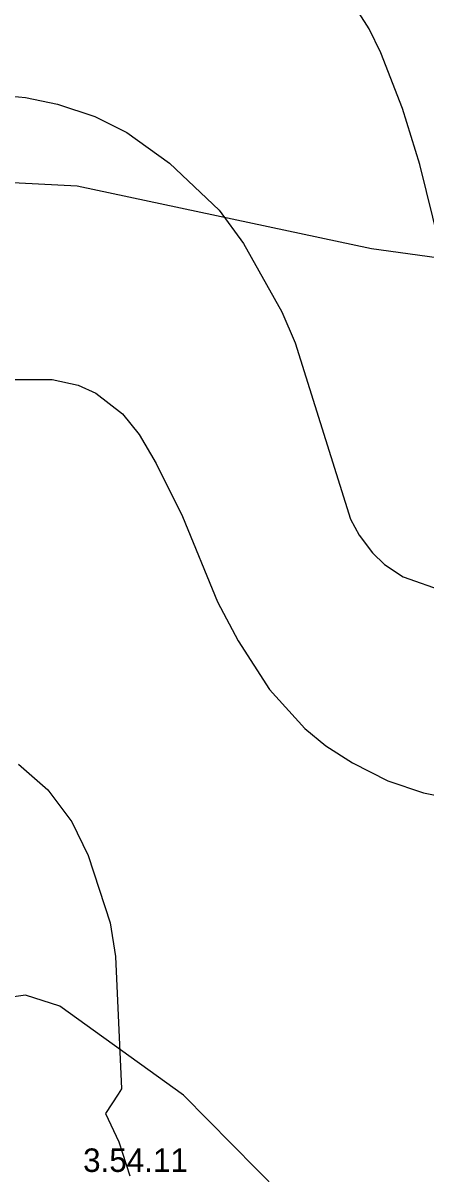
# Model space of a CAD drawing. Extents: x -662500 to -655523, y -1056000 to -1049993.
# Drawn here: x -659925.2 to -659796.6, y -1053965.2 to -1053597.4 of the extents above; entities that cross this region are included whole.
import ezdxf

# ---------------------------------------------------------------- set-up
doc = ezdxf.new("R2010")
doc.units = 0
doc.layers.add('Vrstva 24', color=7, linetype='Continuous')
doc.layers.add('Vrstva 7', color=7, linetype='Continuous')

msp = doc.modelspace()

# ---------------------------------------------------------------- linework, layer by layer
at = {"layer": 'Vrstva 24'}
for points in [[(-659687, -1053701.5), (-659711, -1053686.5), (-659734.5, -1053680.5), (-659814, -1053669.5), (-659908, -1053649.5), (-659980.14, -1053645.8), (-660000, -1053644.78), (-660005.5, -1053644.5), (-660060, -1053634), (-660183.5, -1053621), (-660246.5, -1053605.5), (-660263.5, -1053598), (-660330, -1053557), (-660364, -1053532.5), (-660389, -1053520), (-660401.5, -1053515), (-660430, -1053509.5)], [(-659830.33, -1054000), (-659832, -1053994), (-659843, -1053971.5), (-659874, -1053940), (-659913.5, -1053911.5), (-659924.5, -1053908), (-659938.5, -1053910), (-659952.5, -1053935.5), (-659971.5, -1053994), (-659976.58, -1054000)]]:
    msp.add_lwpolyline(points, dxfattribs=at)
at = {"layer": 'Vrstva 7'}
for p, q in [((-659814.72, -1053599.22), (-659822.94, -1053586.47)), ((-659811.04, -1053606.88), (-659814.72, -1053599.22)), ((-659804.09, -1053624.73), (-659811.04, -1053606.88)), ((-659954.45, -1053618.5), (-659924.41, -1053621.19)), ((-659924.41, -1053621.19), (-659914.21, -1053623.31)), ((-659914.21, -1053623.31), (-659902.3, -1053627.28)), ((-659798.57, -1053642.59), (-659804.09, -1053624.73)), ((-659902.3, -1053627.28), (-659892.1, -1053632.39)), ((-659892.1, -1053632.39), (-659878.49, -1053642.16)), ((-659878.49, -1053642.16), (-659862.62, -1053657.19)), ((-659792.33, -1053668.1), (-659798.57, -1053642.59)), ((-659862.62, -1053657.19), (-659854.83, -1053667.81)), ((-659854.83, -1053667.81), (-659842.64, -1053689.64)), ((-659842.64, -1053689.64), (-659838.39, -1053699.56)), ((-659838.39, -1053699.56), (-659820.67, -1053755.96)), ((-659929.51, -1053711.32), (-659915.91, -1053711.32)), ((-659915.91, -1053711.32), (-659907.69, -1053713.16)), ((-659907.69, -1053713.16), (-659902.02, -1053715.71)), ((-659902.02, -1053715.71), (-659893.52, -1053722.23)), ((-659893.52, -1053722.23), (-659888.13, -1053728.89)), ((-659888.13, -1053728.89), (-659882.74, -1053738.11)), ((-659882.74, -1053738.11), (-659874.38, -1053755.11)), ((-659874.38, -1053755.11), (-659863.19, -1053782.32)), ((-659820.67, -1053755.96), (-659817.98, -1053761.06)), ((-659817.98, -1053761.06), (-659813.73, -1053766.73)), ((-659813.73, -1053766.73), (-659809.9, -1053770.42)), ((-659809.9, -1053770.42), (-659803.95, -1053774.39)), ((-659803.95, -1053774.39), (-659790.63, -1053779.06)), ((-659863.19, -1053782.32), (-659856.53, -1053794.79)), ((-659856.53, -1053794.79), (-659846.61, -1053810.38)), ((-659846.61, -1053810.38), (-659835.27, -1053822.85)), ((-659835.27, -1053822.85), (-659828.61, -1053828.38)), ((-659828.61, -1053828.38), (-659820.11, -1053833.76)), ((-659926.68, -1053834.19), (-659917.32, -1053842.41)), ((-659820.11, -1053833.76), (-659808.77, -1053839.57)), ((-659808.77, -1053839.57), (-659797.43, -1053843.4)), ((-659917.32, -1053842.41), (-659909.67, -1053852.61)), ((-659797.43, -1053843.4), (-659783.83, -1053846.09)), ((-659909.67, -1053852.61), (-659904.43, -1053863.38)), ((-659904.43, -1053863.38), (-659897.48, -1053884.92)), ((-659897.48, -1053884.92), (-659895.78, -1053895.69)), ((-659895.78, -1053895.69), (-659893.84, -1053937.9)), ((-659894.92, -1053939.7), (-659898.87, -1053945.8)), ((-659893.84, -1053937.9), (-659894.92, -1053939.7)), ((-659898.87, -1053945.8), (-659894.65, -1053954.93)), ((-659894.65, -1053954.93), (-659891.11, -1053965.7))]:
    msp.add_line(p, q, dxfattribs=at)

# ---------------------------------------------------------------- texts
at = {"layer": 'Vrstva 24'}
msp.add_text('3.54.11', height=7.5, dxfattribs=at).set_placement((-659906.07, -1053964.5))

doc.saveas('drawing.dxf')
